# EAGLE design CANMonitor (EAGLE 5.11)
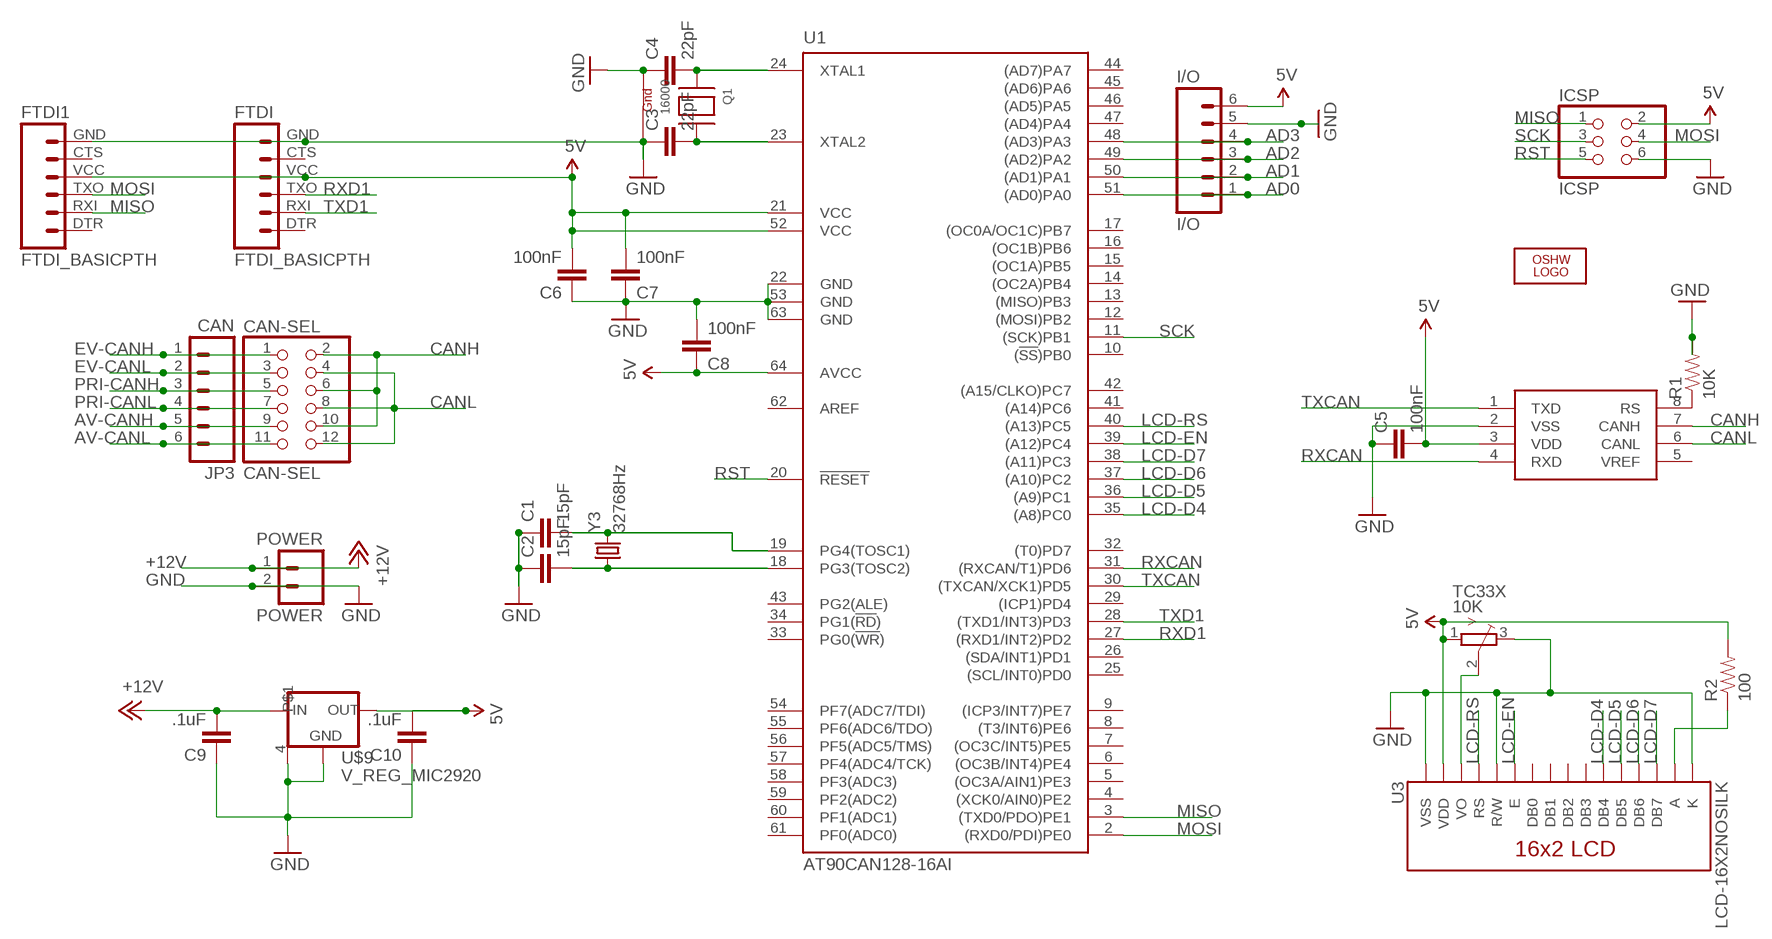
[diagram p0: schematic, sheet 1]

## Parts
C1  15pF  CAP0805  [0805]
C2  15pF  CAP0805  [0805]
C3  22pF  CAP0805  [0805]
C4  22pF  CAP0805  [0805]
C5  100nF  CAP0805  [0805]
C6  100nF  CAP0805  [0805]
C7  100nF  CAP0805  [0805]
C8  100nF  CAP0805  [0805]
C9  .1uF  CAP0805  [0805]
C10  .1uF  CAP0805  [0805]
CAN-SEL  CAN-SEL  PINHD-2X6  [2X06-BIG]
FTDI  FTDI_BASICPTH  [FTDI_BASIC]
FTDI1  FTDI_BASICPTH  [FTDI_BASIC]
I/O  I/O  M06LOCK  [1X06_LOCK]
ICSP  ICSP  PINHD-2X3  [2X03]
JP3  CAN  M063.5MM-6  [SCREWTERMINAL-3.5MM-6]
LOGO2  OSHW_LOGO_10MILX0350-NT  [OSHW_10X350_NOTEXT]
POWER  POWER  M023.5MM_LOCK  [SCREWTERMINAL-3.5MM-2_LOCK]
Q1  16000  XTAL-4-3225  [NX3225]
R1  10K  RESISTOR0805-RES  [0805]
R2  100  RESISTOR0805-RES  [0805]
TC33X  10K  TRIMPOTTC33X  [TC33X]
U1  AT90CAN128-16AI  [TQFP64-0.8MM]
U2  MCP2551  [SO08]
U3  LCD-16X2NOSILK  [LCD-16X2_NOSILK]
U$9  V_REG_MIC2920  [SOT223]
Y3  32768Hz  CRYSTALTC38H  [TC38H]

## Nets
5V: C5.2 C6.2 C7.2 C8.1 C10.2 FTDI1.VCC FTDI.VCC I/O.6 ICSP.2 R2.2 TC33X.1(A) U1.21(VCC) U1.52(VCC) U1.64(AVCC) U2.3(VDD) U3.2(VDD) U$9.3(OUT)
+12V: C9.2 POWER.1 U$9.1(IN)
AD0: I/O.1 U1.51((AD0)PA0)
AD1: I/O.2 U1.50((AD1)PA1)
AD2: I/O.3 U1.49((AD2)PA2)
AD3: I/O.4 U1.48((AD3)PA3)
AV-CANH: CAN-SEL.9 JP3.5
AV-CANL: CAN-SEL.11 JP3.6
CANH: CAN-SEL.2 CAN-SEL.6 CAN-SEL.10 U2.7(CANH)
CANL: CAN-SEL.4 CAN-SEL.8 CAN-SEL.12 U2.6(CANL)
EV-CANH: CAN-SEL.1 JP3.1
EV-CANL: CAN-SEL.3 JP3.2
GND: C1.1 C2.1 C3.1 C4.1 C5.1 C6.1 C7.1 C8.2 C9.1 C10.1 FTDI1.GND FTDI.GND I/O.5 ICSP.6 POWER.2 Q1.1(G1) Q1.3(G2) R1.2 TC33X.3(E) U1.22(GND) U1.53(GND) U1.63(GND) U2.2(VSS) U3.1(VSS) U3.5(R/W) U3.16(K) U$9.2(GND) U$9.4
LCD-D4: U1.35((A8)PC0) U3.11(DB4)
LCD-D5: U1.36((A9)PC1) U3.12(DB5)
LCD-D6: U1.37((A10)PC2) U3.13(DB6)
LCD-D7: U1.38((A11)PC3) U3.14(DB7)
LCD-EN: U1.39((A12)PC4) U3.6(E)
LCD-RS: U1.40((A13)PC5) U3.4(RS)
MISO: FTDI1.RXI ICSP.1 U1.3((TXD0/PDO)PE1)
MOSI: FTDI1.TXO ICSP.4 U1.2((RXD0/PDI)PE0)
N$1: C2.2 U1.18(PG3(TOSC2)) Y3.1
N$2: C4.2 Q1.2(X1) U1.24(XTAL1)
N$3: C1.2 U1.19(PG4(TOSC1)) Y3.2
N$5: R1.1 U2.8(RS)
N$6: C3.2 Q1.4(X2) U1.23(XTAL2)
N$11: TC33X.2(S) U3.3(VO)
N$19: R2.1 U3.15(A)
PRI-CANH: CAN-SEL.5 JP3.3
PRI-CANL: CAN-SEL.7 JP3.4
RST: ICSP.5 U1.20(!RESET)
RXCAN: U1.31((RXCAN/T1)PD6) U2.4(RXD)
RXD1: FTDI.TXO U1.27((RXD1/INT2)PD2)
SCK: ICSP.3 U1.11((SCK)PB1)
TXCAN: U1.30((TXCAN/XCK1)PD5) U2.1(TXD)
TXD1: FTDI.RXI U1.28((TXD1/INT3)PD3)
Unconnected: FTDI1.CTS FTDI1.DTR FTDI.CTS FTDI.DTR U1.4((XCK0/AIN0)PE2) U1.5((OC3A/AIN1)PE3) U1.6((OC3B/INT4)PE4) U1.7((OC3C/INT5)PE5) U1.8((T3/INT6)PE6) U1.9((ICP3/INT7)PE7) U1.10((!SS!)PB0) U1.12((MOSI)PB2) U1.13((MISO)PB3) U1.14((OC2A)PB4) U1.15((OC1A)PB5) U1.16((OC1B)PB6) U1.17((OC0A/OC1C)PB7) U1.25((SCL/INT0)PD0) U1.26((SDA/INT1)PD1) U1.29((ICP1)PD4) U1.32((T0)PD7) U1.33(PG0(!WR!)) U1.34(PG1(!RD!)) U1.41((A14)PC6) U1.42((A15/CLKO)PC7) U1.43(PG2(ALE)) U1.44((AD7)PA7) U1.45((AD6)PA6) U1.46((AD5)PA5) U1.47((AD4)PA4) U1.54(PF7(ADC7/TDI)) U1.55(PF6(ADC6/TDO)) U1.56(PF5(ADC5/TMS)) U1.57(PF4(ADC4/TCK)) U1.58(PF3(ADC3)) U1.59(PF2(ADC2)) U1.60(PF1(ADC1)) U1.61(PF0(ADC0)) U1.62(AREF) U2.5(VREF) U3.7(DB0) U3.8(DB1) U3.9(DB2) U3.10(DB3)

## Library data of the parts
C1-C10 = SparkFun:CAP: Capacitor
CAN-SEL = lincomatic:PINHD-2X6: PIN HEADER With larger annulars
FTDI FTDI1 = SparkFun:FTDI_BASIC: FTDI Basic: 3.3V and 5V
I/O JP3 = SparkFun:M06: Header 6 Standard 6-pin 0.1" header. Use with straight break away headers (SKU : PRT-00116), right angle break away headers (PRT-00553), swiss pins (PRT-00743), machine pins (PRT-00117), and female headers (PRT-00115). Molex polarized connector foot print use with SKU : PRT-08094 with associated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
ICSP = SparkFun:PINHD-2X3: PIN HEADER
LOGO2 = ohw-logo:OSHW_LOGO_10MIL
POWER = SparkFun:M02: Header 2
Q1 = adafruit:XTAL-4: Classic 4-pin 3.2 x 2.5mm crystal
R1 R2 = SparkFun:RESISTOR: Resistor
TC33X = adafruit:TRIMPOT: SMT trimmer potentiometer part number TC33X http://www.ladyada.net/library/eagle
U1 = _hhn_at90can32_64_128_v2:AT90CAN*: ATMEL AVR AT90CAN32-..A. / 64-..A. / 128-..A., TQFP64 with 0.8mm pad spacing (Atmel Package Code 'A2 64': 64-Lead, Thin 1.0 mm / 0.03937 in. Plastic Gull Wing Quad Flat Package) Ordering Code = Product Marking / Speed (MHz) / Power Supply (V) / Operation Range AT90CANx-16AI / 16 / 2.7 .. 5.5 /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
U2 = SparkFun:MCP2551
U3 = SparkFun:LCD-16X2
U$9 = SparkFun:V_REG_MIC2920: MIC2920A (http://www.micrel.com/_PDF/mic2920.pdf) - 400mA output LDO Regulator
Y3 = SparkFun:CRYSTAL: Crystals

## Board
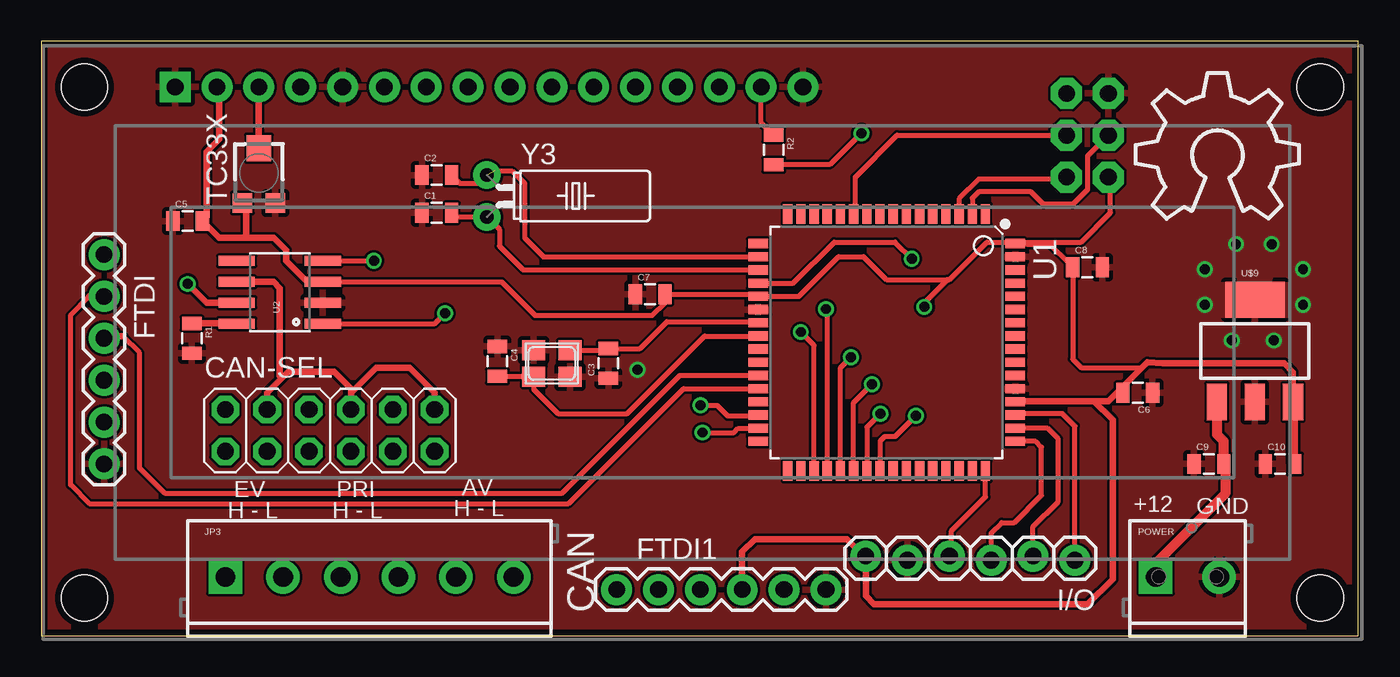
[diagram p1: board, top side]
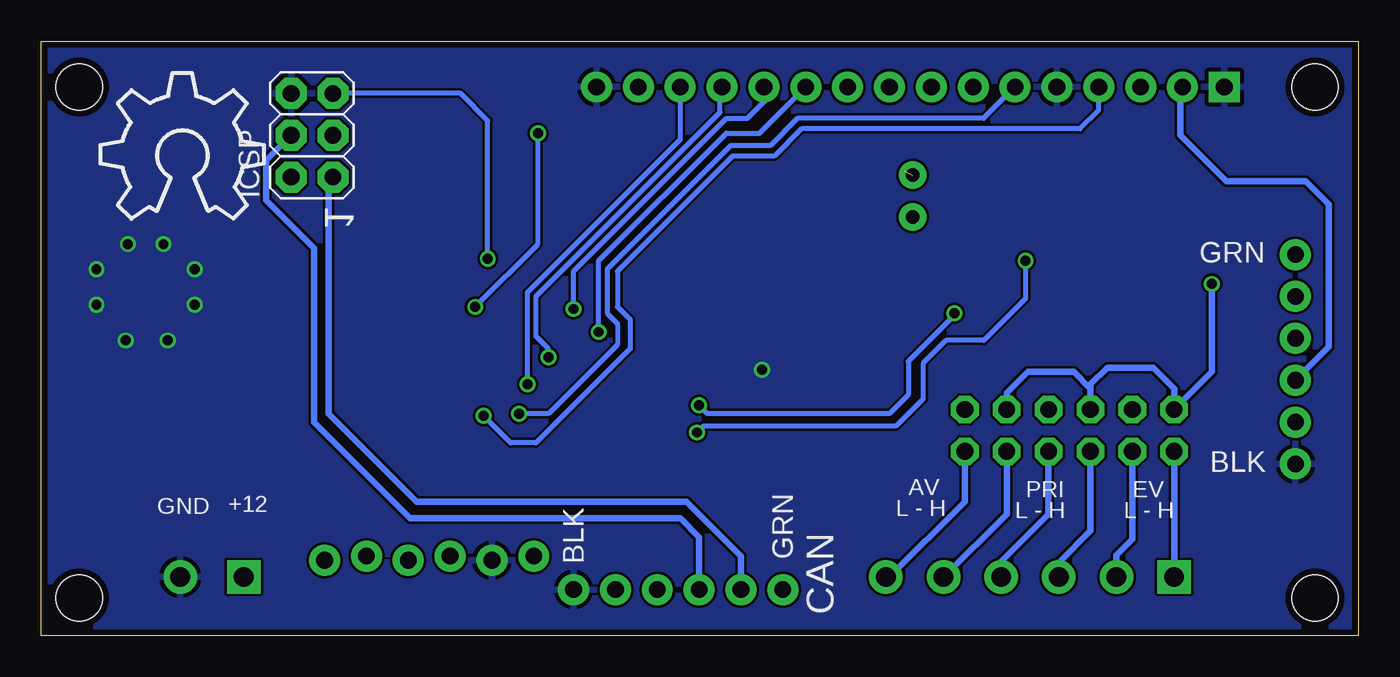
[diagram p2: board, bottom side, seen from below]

Size 79.93 x 36.06 mm. Coordinates in mm from the lower left corner, seen from the top.
Outline: 0,0 79.93,0 79.93,36.06 0,36.06 0,0
Copper layers (1*16): Top 0.0356mm / dielectric 1.5011mm / Bottom 0.0356mm
Design rules "LaenPCBOrder": minimum track width 6mil, minimum drill 13mil, track to track 6mil, track to pad 6mil, pad to pad 6mil, via to via 6mil, smd to smd 6mil, copper to edge 15mil, drill to drill 6mil, minimum pad ring 7mil, minimum via ring 7mil, stop-mask expansion 4mil, vias tented up to drill 0mil, thermal gap 10mil

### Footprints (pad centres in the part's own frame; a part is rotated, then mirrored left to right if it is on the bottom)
0805 = smd 0.8 x 1.2: 1 -0.9,0; 2 0.9,0
2X06-BIG = drill 1.016 pad 1.676 octagon: 1 -6.35,-1.27; 2 -6.35,1.27; 3 -3.81,-1.27; 4 -3.81,1.27; 5 -1.27,-1.27; 6 -1.27,1.27; 7 1.27,-1.27; 8 1.27,1.27; 9 3.81,-1.27; 10 3.81,1.27; 11 6.35,-1.27; 12 6.35,1.27
FTDI_BASIC = drill 1.016 pad 1.88 round: CTS 10.16,0; DTR 0,0; GND 12.7,0; RXI 2.54,0; TXO 5.08,0; VCC 7.62,0
1X06_LOCK = drill 1.016 pad 1.88 round: 1 0,0; 2 2.54,-0.254; 3 5.08,0; 4 7.62,-0.254; 5 10.16,0; 6 12.7,-0.254
2X03 = drill 1.016 pad 1.88 octagon: 1 -2.54,-1.27; 2 -2.54,1.27; 3 0,-1.27; 4 0,1.27; 5 2.54,-1.27; 6 2.54,1.27
SCREWTERMINAL-3.5MM-6 = drill 1.2 pad 2.032 square: 1 0,0 | drill 1.2 pad 2.032 round: 2 3.5,0; 3 7,0; 4 10.5,0; 5 14,0; 6 17.5,0
SCREWTERMINAL-3.5MM-2_LOCK = drill 1.2 pad 2.032 square: 1 -0.178,0 | drill 1.2 pad 2.032 round: 2 3.678,0
NX3225 = smd 1.4 x 1.2: 1 -1.1,0.8; 2 1.1,0.8; 3 1.1,-0.8; 4 -1.1,-0.8
TC33X = smd 1.2 x 1.2: 1 -1,-1.825; 3 1,-1.825 | smd 1.5 x 1.6: 2 0,1.5
TQFP64-0.8MM = smd 1.194 x 0.559: 1 -7.8,6; 2 -7.8,5.2; 3 -7.8,4.4; 4 -7.8,3.6; 5 -7.8,2.8; 6 -7.8,2; 7 -7.8,1.2; 8 -7.8,0.4; 9 -7.8,-0.4; 10 -7.8,-1.2; 11 -7.8,-2; 12 -7.8,-2.8; 13 -7.8,-3.6; 14 -7.8,-4.4; 15 -7.8,-5.2; 16 -7.8,-6; 33 7.8,-6; 34 7.8,-5.2; 35 7.8,-4.4; 36 7.8,-3.6; 37 7.8,-2.8; 38 7.8,-2; 39 7.8,-1.2; 40 7.8,-0.4; 41 7.8,0.4; 42 7.8,1.2; 43 7.8,2; 44 7.8,2.8; 45 7.8,3.6; 46 7.8,4.4; 47 7.8,5.2; 48 7.8,6 | smd 0.559 x 1.194: 17 -6,-7.8; 18 -5.2,-7.8; 19 -4.4,-7.8; 20 -3.6,-7.8; 21 -2.8,-7.8; 22 -2,-7.8; 23 -1.2,-7.8; 24 -0.4,-7.8; 25 0.4,-7.8; 26 1.2,-7.8; 27 2,-7.8; 28 2.8,-7.8; 29 3.6,-7.8; 30 4.4,-7.8; 31 5.2,-7.8; 32 6,-7.8; 49 6,7.8; 50 5.2,7.8; 51 4.4,7.8; 52 3.6,7.8; 53 2.8,7.8; 54 2,7.8; 55 1.2,7.8; 56 0.4,7.8; 57 -0.4,7.8; 58 -1.2,7.8; 59 -2,7.8; 60 -2.8,7.8; 61 -3.6,7.8; 62 -4.4,7.8; 63 -5.2,7.8; 64 -6,7.8
SO08 = smd 0.61 x 2.21: 1 -1.905,-2.616; 2 -0.635,-2.616; 3 0.635,-2.616; 4 1.905,-2.616; 5 1.905,2.616; 6 0.635,2.616; 7 -0.635,2.616; 8 -1.905,2.616
LCD-16X2_NOSILK = drill 1.016 pad 1.88 square: 1 -32,15.5 | drill 1.016 pad 1.88 round: 2 -29.46,15.5; 3 -26.92,15.5; 4 -24.38,15.5; 5 -21.84,15.5; 6 -19.3,15.5; 7 -16.76,15.5; 8 -14.22,15.5; 9 -11.68,15.5; 10 -9.14,15.5; 11 -6.6,15.5; 12 -4.06,15.5; 13 -1.52,15.5; 14 1.02,15.5; 15 3.56,15.5; 16 6.1,15.5 | hole 2.8: -37.5,15.5; -37.5,-15.5; 37.5,15.5; 37.5,-15.5
SOT223 = smd 1.219 x 2.235: 1 -2.311,-3.099; 2 0,-3.099; 3 2.311,-3.099 | smd 3.6 x 2.2: 4 0,3.099
TC38H = drill 0.813 pad 1.676 round: 1 -1.27,0; 2 1.27,0

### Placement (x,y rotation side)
C1  24,25.65 0 top
C2  24,27.94 0 top
C3  34.42,16.51 90 top
C4  27.69,16.64 270 top
C5  8.89,25.15 0 top
C6  66.55,14.73 180 top
C7  36.96,20.7 0 top
C8  63.5,22.35 0 top
C9  70.87,10.41 0 top
C10  75.18,10.41 0 top
CAN-SEL  17.53,12.45 0 top
FTDI  3.81,23.11 270 top
FTDI1  34.92,2.79 0 top
I/O  62.74,4.57 180 top
ICSP  63.5,30.35 90 bottom
JP3  11.18,3.56 0 top
LOGO1  OSHW_LOGO_10MILX0350-NT  [OSHW_10X350_NOTEXT]  66.42,25.27 0 top
LOGO2  76.33,25.27 0 bottom
POWER  67.82,3.56 0 top
Q1  30.99,16.51 180 top
R1  9.14,18.03 270 top
R2  44.45,29.46 270 top
TC33X  13.21,28.07 0 top
U1  51.31,17.78 270 top
U2  14.48,20.83 90 top
U3  40.13,17.78 0 top
U$9  73.66,17.27 0 top
Y3  27.05,26.67 270 top

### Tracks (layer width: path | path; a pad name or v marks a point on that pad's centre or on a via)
5V  (via drill 0.6)
  Top 0.305: U2.3 27.94,21.46 29.97,19.43 37.08,19.43 37.85,20.19 37.85,20.69 C7.2 43.39,20.7 U1.21 45.98,20.58 48.39,22.99 49.91,22.99 51.31,21.59 54.99,21.59 | 54.99,21.59 55.12,21.59 57.4,23.88 59.01,23.88 U1.64 59.2,23.88 59.69,23.88 | v53.59,19.94 53.59,20.19 54.99,21.59 | 67.12,16.57 66.8,16.26 63.12,16.26 62.6,16.77 C8.1 62.61,22.47 62.36,22.61 61.21,23.75 59.82,23.75 59.69,23.88 | 59.69,23.88 63.12,23.88 64.9,25.65 64.9,27.69 ICSP.2 | R2.2 47.87,28.56 v49.78,30.48 | C6.2 65.28,14.73 65.15,14.61
  Top 0.406: 63.88,14.22 59.15,14.22 U1.52 | 63.88,14.22 64.77,14.22 65.15,14.61 67.12,16.57 68.07,16.51 75.44,16.51 75.97,15.98 U$9.3 76.15,14.35 | U2.3 16.13,21.46 14.86,22.73 14.86,23.37 14.1,24.13 12.45,24.13 | 12.45,24.13 10.81,24.13 C5.2 10.04,25.4 10.04,29.35 10.79,30.1 10.79,33.16 U3.2 | 50.04,4.7 I/O.6 | 63.88,14.22 65.02,13.08 65.02,3.43 63.5,1.91 50.55,1.91 50.04,2.41 50.04,4.7 | 50.04,4.7 48.9,5.84 43.31,5.84 42.55,5.08 FTDI1.VCC | TC33X.1 12.45,26.24 12.45,24.13
  Top 0.61: U$9.3 75.97,10.53 C10.2
  Bottom 0.305: v49.78,30.48 49.78,23.75 v53.59,19.94
  Bottom 0.406: U3.2 10.79,33.16 10.79,30.35 8,27.56 3.17,27.56 1.78,26.16 1.78,17.53 FTDI.VCC
+12V
  Top 0.61: POWER.1 67.64,4.39 71.88,8.64 71.88,10.3 C9.2 71.77,11.8 71.37,12.19 71.37,14.15 U$9.1
AD0
  Top 0.305: I/O.1 62.74,12.7 61.98,13.46 59.19,13.46 U1.51
AD1
  Top 0.305: I/O.2 60.2,6.6 61.72,8.13 61.72,11.94 61.09,12.57 U1.50
AD2
  Top 0.305: U1.49 60.36,11.78 60.71,11.43 60.71,8.51 59.05,6.86 58.29,6.86 57.66,6.22 I/O.3
AD3
  Top 0.305: U1.48 57.31,8.41 55.24,6.35 55.24,4.95 I/O.4
AV-CANH
  Bottom 0.406: JP3.5 25.15,3.56 21.34,7.37 CAN-SEL.9
AV-CANL
  Bottom 0.406: JP3.6 28.45,3.56 23.88,8.13 CAN-SEL.11
CANH  (via drill 0.6)
  Top 0.406: U2.7 10.03,20.19 v8.89,21.34
  Bottom 0.406: 16.26,14.99 16.26,15.24 15.24,16.26 12.45,16.26 11.18,14.99 CAN-SEL.2 8.89,16 v8.89,21.34 | 16.26,14.99 CAN-SEL.6 | CAN-SEL.10 21.34,14.73 20.07,16 17.27,16 16.26,14.99
CANL
  Top 0.406: CAN-SEL.12 23.88,14.73 22.35,16.26 20.32,16.26 18.8,14.73 CAN-SEL.8 18.8,14.99 17.78,16 14.99,16 14.61,15.62 | CAN-SEL.4 13.72,14.73 14.61,15.62 | U2.6 14.1,21.46 14.48,21.08 14.48,15.75 14.61,15.62
EV-CANH
  Bottom 0.406: JP3.1 CAN-SEL.1
EV-CANL
  Bottom 0.406: JP3.2 14.68,4.88 13.72,5.84 CAN-SEL.3
GND  (via drill 0.6)
  other vias: 36.2,16.13 70.61,20.07 70.61,22.23 72.52,23.75 74.68,23.75 76.58,22.23 76.58,20.07 72.26,17.91 74.8,17.91
  pour Top: -8.64,-13.97 94.23,-13.97 94.23,53.34 -8.64,53.34
  pour Bottom: -6.35,-5.84 86.11,-5.84 86.11,43.94 -6.35,43.94 -6.35,-5.08
  pour Top (isolate 2.54): 71.88,21.59 75.69,21.72 75.56,18.92 71.75,18.92 71.88,21.72
LCD-D4  (via drill 0.6)
  Top 0.305: U1.35 46.91,17.61 v46.1,18.41
  Bottom 0.305: v46.1,18.41 46.1,22.73 38.35,30.48 36.33,30.48 U3.11
LCD-D5  (via drill 0.6)
  Top 0.305: U1.36 47.71,19.73 v47.62,19.81
  Bottom 0.305: v47.62,19.81 47.62,22.1 38.35,31.37 37.08,31.37 35.94,32.51 35.94,33.15 U3.12
LCD-D6  (via drill 0.6)
  Top 0.305: U1.37 48.51,16.25 v49.15,16.89
  Bottom 0.305: v49.15,16.89 49.15,17.4 49.91,18.16 49.91,20.57 38.73,31.75 38.73,33.16 U3.13
LCD-D7  (via drill 0.6)
  Top 0.305: U1.38 49.31,14.13 v50.42,15.24
  Bottom 0.305: v50.42,15.24 50.42,20.83 41.15,30.1 U3.14
LCD-EN  (via drill 0.6)
  Top 0.305: U1.39 50.11,12.64 v50.93,13.46
  Bottom 0.305: v50.93,13.46 49.15,13.46 44.96,17.65 44.96,18.92 45.59,19.56 45.59,22.23 38.1,29.72 35.69,29.72 34.04,31.37 22.74,31.37 U3.6
LCD-RS  (via drill 0.6)
  Top 0.305: U1.40 50.91,11.79 51.18,12.06 51.82,12.06 v53.09,13.34
  Bottom 0.305: v53.09,13.34 51.44,11.68 49.91,11.68 44.2,17.4 44.2,19.18 44.96,19.94 44.96,22.1 37.97,29.08 35.43,29.08 33.78,30.73 16.89,30.73 15.75,31.88 U3.4
MISO
  Top 0.305: U1.3 55.71,26.5 56.9,27.69 62.1,27.69 ICSP.1
  Bottom 0.406: FTDI1.RXI 37.47,4.83 40.77,8.13 57.15,8.13 62.48,13.46 62.48,27.56 ICSP.1
MOSI
  Top 0.305: ICSP.4 63.5,29.08 63.5,27.05 62.61,26.16 60.83,26.16 60.07,26.92 56.9,26.92 56.51,26.54 U1.2
  Bottom 0.406: FTDI1.TXO 40.01,5.97 41.15,7.11 57.53,7.11 63.37,12.95 63.37,23.5 66.29,26.42 66.29,28.83 ICSP.4
N$1  (1 unrouted)
  Top 0.305: U1.18 30.49,22.98 29.34,24.13 29.34,27.43 28.57,28.19 27.56,28.19 26.8,27.43 25.41,27.43 C2.2
N$2
  Top 0.305: C4.2 29.86,15.74 Q1.2 29.89,14.94 31.37,13.46 35.56,13.46 40.26,18.16 43.49,18.16 U1.24
N$3
  Top 0.305: U1.19 29.25,22.18 27.81,23.62 27.81,24.64 Y3.2 25.16,25.4 C1.2
N$5
  Top 0.406: R1.1 11.85,18.93 U2.8
N$6
  Top 0.305: Q1.4 34.32,17.31 C3.2 36.33,17.41 37.97,19.05 43.44,19.05 U1.23
N$11
  Top 0.406: TC33X.2 U3.3
N$19
  Top 0.305: U3.15 43.69,31.12 R2.1
PRI-CANH
  Bottom 0.406: JP3.3 18.18,4.43 16.26,6.35 CAN-SEL.5
PRI-CANL
  Bottom 0.406: JP3.4 21.68,4.49 18.8,7.37 CAN-SEL.7
RST  (via drill 0.6)
  Top 0.305: U1.20 45.64,21.38 48.13,23.88 51.82,23.88 v52.83,22.86
  Bottom 0.305: v52.83,22.86 52.83,31.24 54.48,32.89 ICSP.5
RXCAN  (via drill 0.6)
  Top 0.305: v40.13,12.32 42.04,12.32 42.29,12.57 U1.31 | U2.4 v20.19,22.73
  Bottom 0.305: v40.13,12.32 39.75,12.7 28.07,12.7 26.42,14.35 26.42,16.51 25.02,17.91 22.73,17.91 20.19,20.45 v20.19,22.73
RXD1
  Top 0.305: U1.27 38.77,15.78 31.62,8.64 7.49,8.64 5.97,10.16 5.97,17.14 4.95,18.16
  Top 0.406: 4.95,18.16 3.94,18.16 FTDI.TXO
SCK
  Top 0.305: ICSP.3 51.94,30.35 49.4,27.81 49.4,25.68 U1.11
TXCAN  (via drill 0.6)
  Top 0.305: v40.01,13.97 41.02,13.97 41.66,13.34 43.46,13.34 U1.30 | U2.1 23.88,18.92 v24.51,19.56
  Bottom 0.305: v40.01,13.97 39.5,13.46 28.45,13.46 27.3,14.61 27.3,16.64 24.51,19.43 v24.51,19.56
TXD1
  Top 0.305: 2.92,20.57 1.78,19.43 1.78,9.14 2.92,8 32,8 38.99,14.99 U1.28
  Top 0.406: 2.92,20.57 FTDI.RXI

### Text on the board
tNames: AV | EV | PRI | H - L | H - L | H - L | +12 | GND | CAN
bNames: 1 | GRN | BLK | AV | GRN | L - H | EV | L - H | PRI | L - H | BLK | +12 | GND | CAN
